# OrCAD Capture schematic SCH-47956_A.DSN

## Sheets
1 01_TITLE: title: OM29110RPI-B; rev: A; note: SCH-47956 PDF: SPF-47956
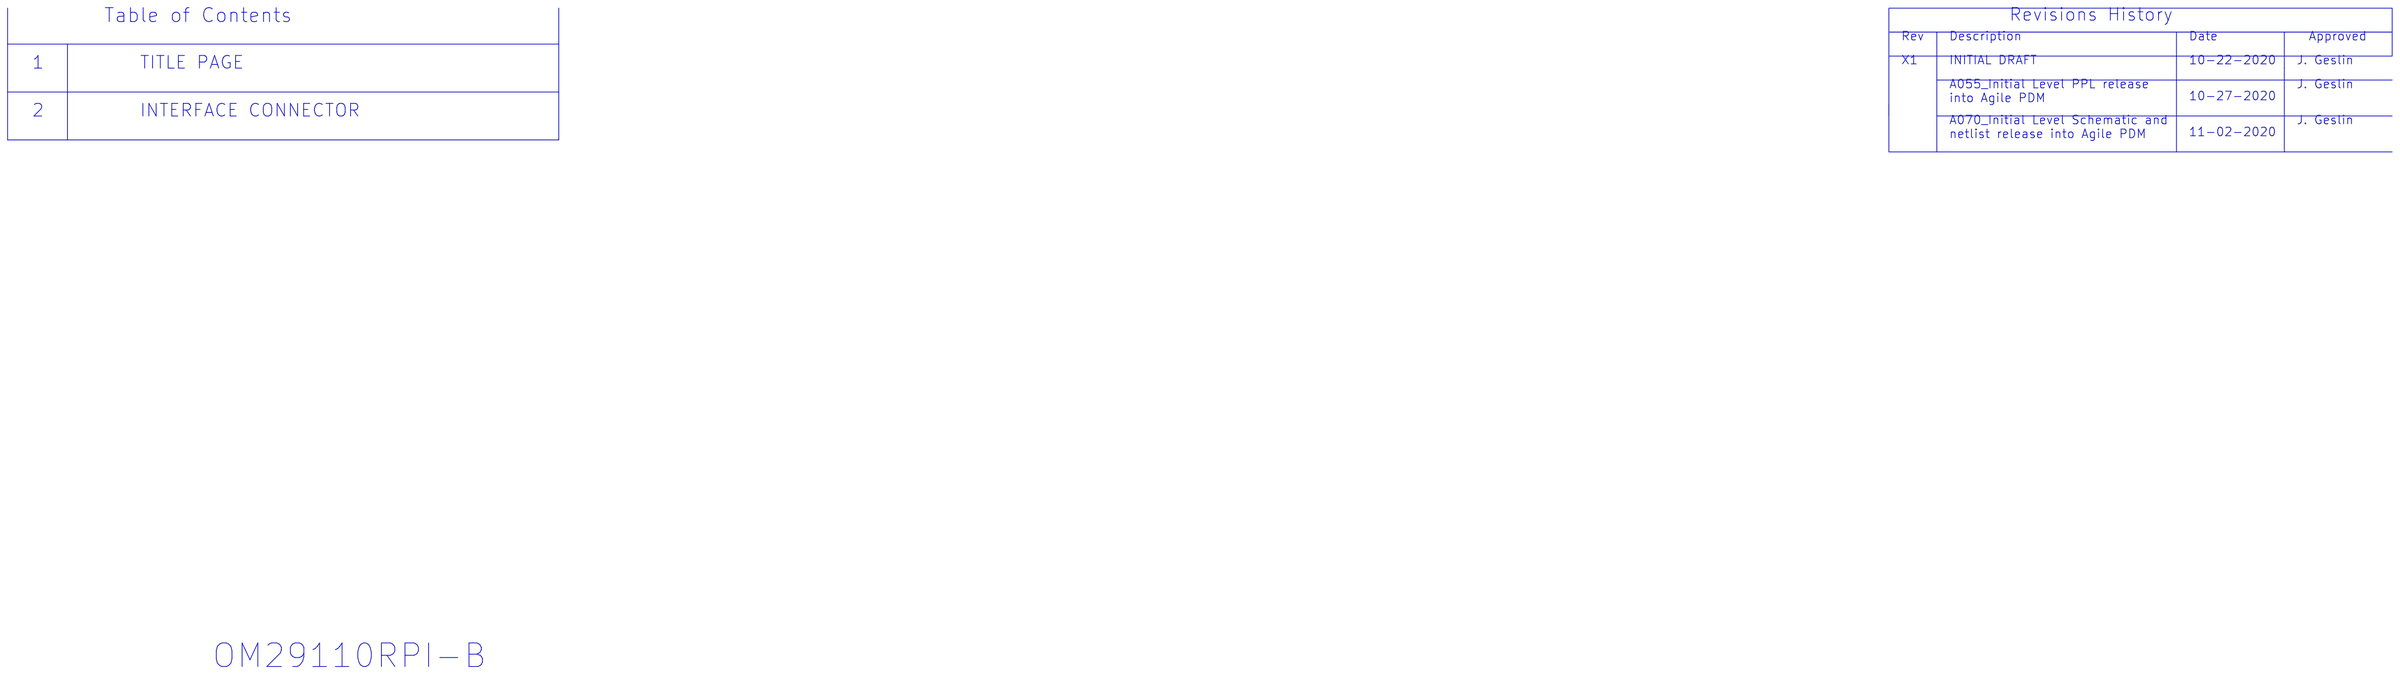
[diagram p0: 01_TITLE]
2 02_INTERFACE CONNECTORS: size C; company: NXP Semiconductors; note: 6501 William Cannon Drive West; note: Austin, TX 78735-8598
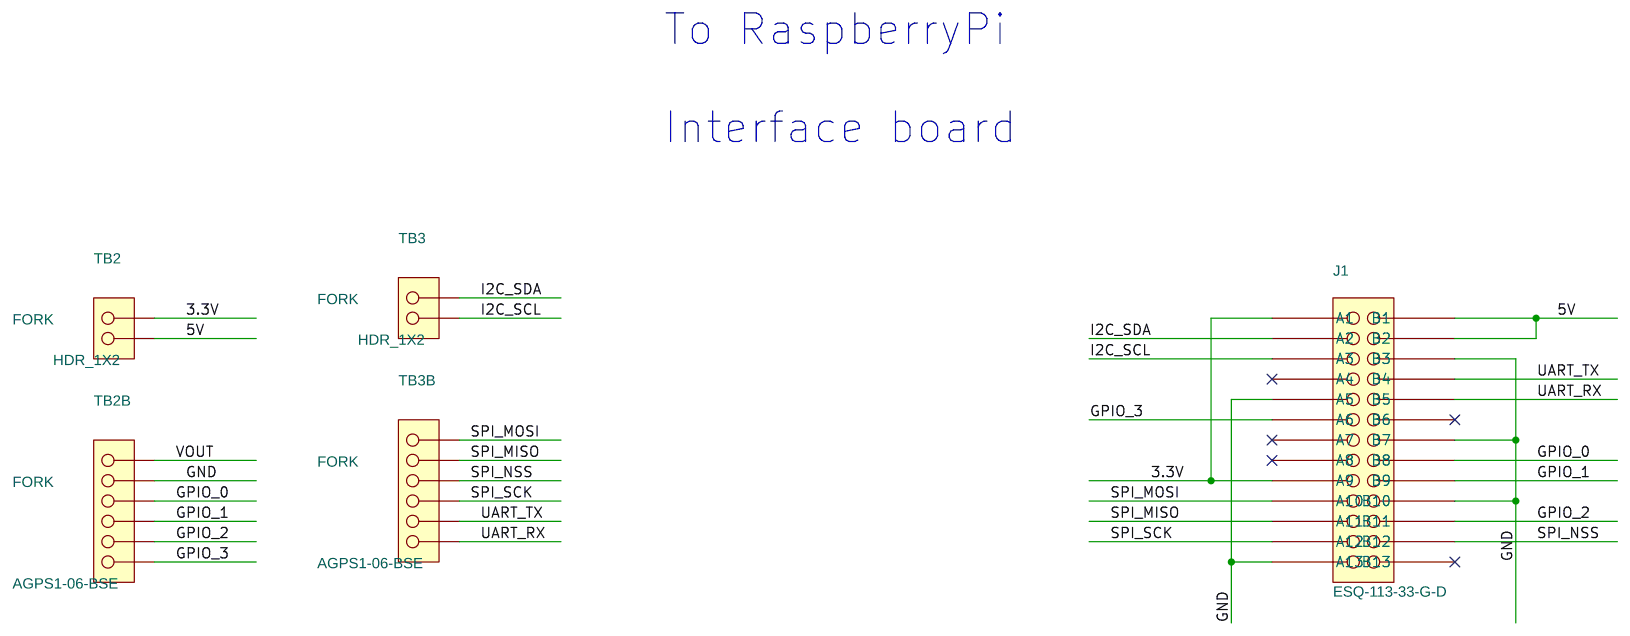
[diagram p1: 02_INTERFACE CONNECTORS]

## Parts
J1  ESQ-113-33-G-D  [hdr2x13_2p54_th_esq]
TB2  HDR_1X2  [skt1x2_2p54_th_bse]
TB2B  AGPS1-06-BSE  [skt1x6_2p54_th_bse]
TB3  HDR_1X2  [skt1x2_2p54_th_bse]
TB3B  AGPS1-06-BSE  [skt1x6_2p54_th_bse]

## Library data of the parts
J1 = CONN_HDR_13X2: CON 2X13 SKT SHRD TH 100MIL CTR 645H AU 90L; AGILE_PN: 210-81713; HEIGHT: 16.4MM; MFG_NAME01: SAMTEC; ROHS: Yes; Temp Range: -55°C ~ 125°C
TB2 TB3 = CONN_HDR_2X1: CON 1X2 SKT TH 100MIL SP 276H SN 196L; AGILE_PN: 210-82543; CAD_APPROVED: Yes; Contact Voltage: 1000Vrms; HEIGHT: 7.0MM; MFG_NAME01: ANTELEC; MFG_PN01: AGPS1-02-BSE-1MM3; Package Size: 5.08 x2.5mm; Package Type: CON HDR TH; ROHS: Yes; SILK: FORK; Temp Range: -55C to +125C
TB2B TB3B = CONN_HDR_6X1: CON 1X6 TB TH 100MIL 276H SN 196L; AGILE_PN: 210-81709; CAD_APPROVED: Yes; HEIGHT: 7MM; MFG_NAME01: ANTELEC; ROHS: Yes; SILK: FORK; Temp Range: -55°C ~ 125°C

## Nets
3.3V: J1.1(A1) J1.17(A9) TB2.1
5V: J1.2(B1) J1.4(B2) TB2.2
GND: J1.6(B3) J1.9(A5) J1.14(B7) J1.20(B10) J1.25(A13) TB2B.2
GPIO_0: J1.16(B8) TB2B.3
GPIO_1: J1.18(B9) TB2B.4
GPIO_2: J1.22(B11) TB2B.5
GPIO_3: J1.11(A6) TB2B.6
I2C_SCL: J1.5(A3) TB3.2
I2C_SDA: J1.3(A2) TB3.1
SPI_MISO: J1.21(A11) TB3B.2
SPI_MOSI: J1.19(A10) TB3B.1
SPI_NSS: J1.24(B12) TB3B.3
SPI_SCK: J1.23(A12) TB3B.4
UART_RX: J1.10(B5) TB3B.6
UART_TX: J1.8(B4) TB3B.5
VOUT: TB2B.1

Not connected (* = marked no-connect by the designer): J1 7(A4)* 12(B6)* 13(A7)* 15(A8)* 26(B13)*

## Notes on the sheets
sheet 1
- Table of Contents
- Revisions History
- Rev
- Description
- Date
- Approved
- 1
- TITLE PAGE
- X1
- INITIAL DRAFT
- 10-22-2020
- J. Geslin
- A055_Initial Level PPL release
  into Agile PDM
- J. Geslin
- 10-27-2020
- 2
- INTERFACE CONNECTOR
- A070_Initial Level Schematic and
  netlist release into Agile PDM
- J. Geslin
- 11-02-2020
- OM29110RPI-B
sheet 2
- To RaspberryPi
  Interface board
